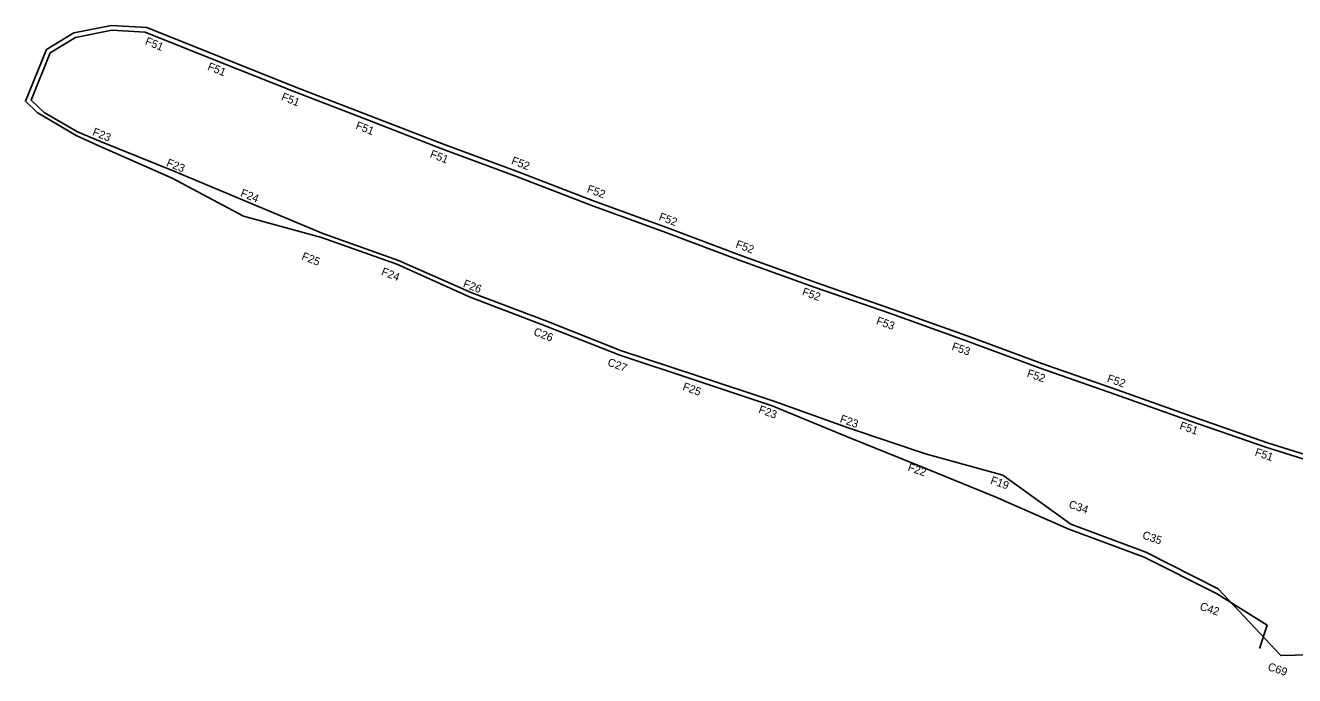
# Model space of a CAD drawing. Extents: x 2165700 to 2171741, y 206405 to 209505.
# Drawn here: x 2165700 to 2166493, y 209099 to 209505 of the extents above; entities that cross this region are included whole.
import ezdxf

# ---------------------------------------------------------------- set-up
doc = ezdxf.new("R2010")
doc.units = 0
for name, color, linetype in [('RD_PD_CstnLmt', 7, 'Continuous'), ('RD_PD_DR_ErosCtrl', 7, 'Continuous'), ('RD_PD_TX_CstnLmt', 7, 'Continuous')]:
    doc.layers.add(name, color=color, linetype=linetype)

msp = doc.modelspace()

# ---------------------------------------------------------------- linework, layer by layer
at = {"layer": 'RD_PD_CstnLmt'}
for points in [[(2165747.21, 209432.71), (2165732.71, 209438.76), (2165712.04, 209450.85), (2165703.77, 209458.61), (2165715.77, 209488.06), (2165731.53, 209497.76), (2165754.23, 209502.23), (2165775.05, 209501.06)], [(2165775.05, 209501.06), (2165821.27, 209482.56), (2165867.5, 209464.07), (2165913.95, 209446.14), (2165960.36, 209428.13), (2166007.07, 209410.87), (2166053.52, 209392.96), (2166100.26, 209375.82), (2166146.89, 209358.39), (2166193.74, 209341.54), (2166240.75, 209325.16), (2166287.63, 209308.42), (2166334.32, 209291.12), (2166381.27, 209274.58), (2166428.2, 209257.95), (2166475.23, 209241.61), (2166522.74, 209226.69)], [(2165747.21, 209432.71), (2165793.68, 209414), (2165839.83, 209394.47), (2165886.05, 209375.12), (2165933.27, 209358.3), (2165979.19, 209338.13), (2166026.05, 209320.39), (2166072.64, 209301.91), (2166120.24, 209286.15), (2166167.83, 209270.41), (2166214.97, 209253.46), (2166262.49, 209237.55), (2166310.85, 209224.11), (2166353.29, 209193.57), (2166400.26, 209175.98), (2166445.47, 209153.07), (2166484.54, 209111.46), (2166537.83, 209112.65)]]:
    msp.add_lwpolyline(points, dxfattribs=at)
at = {"layer": 'RD_PD_DR_ErosCtrl'}
for points in [[(2165707.57, 209450.82), (2165700.21, 209457.83), (2165713.36, 209490.1), (2165730.42, 209500.59), (2165754.02, 209505.25), (2165776.16, 209503.85)], [(2165776.16, 209503.85), (2165822.39, 209485.35), (2165868.6, 209466.86), (2165915.03, 209448.94), (2165961.43, 209430.93), (2166008.13, 209413.68), (2166054.58, 209395.77), (2166101.3, 209378.63), (2166147.93, 209361.21), (2166194.74, 209344.37), (2166241.75, 209327.99), (2166288.66, 209311.24), (2166335.34, 209293.94), (2166382.27, 209277.41), (2166429.19, 209260.78), (2166476.17, 209244.45), (2166523.61, 209229.56), (2166571.33, 209215.43), (2166619.35, 209201.82), (2166668.5, 209189), (2166668.5, 209189)], [(2165707.57, 209450.82), (2165732, 209436.48), (2165746.06, 209429.89), (2165792.01, 209409.85), (2165792.01, 209409.85), (2165836.5, 209386.09), (2165885.13, 209372.77), (2165932.36, 209355.94), (2165978.11, 209335.3), (2166024.93, 209317.48), (2166024.93, 209317.48), (2166024.95, 209317.47), (2166071.58, 209299.08), (2166119.2, 209283.34), (2166166.79, 209267.54), (2166213.15, 209248.37), (2166259.64, 209229.54), (2166306.15, 209210.68), (2166352.22, 209190.49), (2166399.23, 209172.94), (2166444.5, 209150.19), (2166476.04, 209130.33), (2166471.25, 209115.87)]]:
    msp.add_lwpolyline(points, dxfattribs=at)

# ---------------------------------------------------------------- texts
at = {"layer": 'RD_PD_TX_CstnLmt'}
for s, rotation, p in [('F51', 337.83882, (2165774.6, 209493.53)), ('F51', 338.07756, (2165813.59, 209477.66)), ('F51', 338.31629, (2165859.68, 209458.74)), ('F51', 338.55502, (2165906.14, 209440.82)), ('F23', 337.83882, (2165741.69, 209436.86)), ('F23', 338.07756, (2165787.92, 209417.56)), ('F51', 338.79375, (2165952.58, 209422.97)), ('F52', 339.03249, (2166003.4, 209418.8)), ('F52', 339.27122, (2166050.63, 209401.12)), ('F24', 338.31629, (2165834.16, 209398.64)), ('F52', 339.50995, (2166095.58, 209383.74)), ('F52', 339.74868, (2166143.53, 209366.56)), ('F25', 338.55502, (2165872.39, 209359.1)), ('F24', 338.79375, (2165922.17, 209349.5)), ('F26', 339.03249, (2165973.28, 209341.95)), ('F52', 339.98742, (2166185.09, 209336.89)), ('F53', 340.22615, (2166231.41, 209318.68)), ('C26', 339.27122, (2166017.29, 209311.89)), ('F53', 340.46488, (2166278.58, 209302.63)), ('C27', 339.50995, (2166063.51, 209292.85)), ('F52', 340.70361, (2166325.53, 209285.86)), ('F52', 340.94235, (2166375.61, 209282.6)), ('F25', 339.74868, (2166110.45, 209277.63)), ('F23', 339.98742, (2166157.86, 209263.29)), ('F23', 340.22615, (2166208.7, 209257.41)), ('F51', 341.18108, (2166420.94, 209253.07)), ('F51', 341.41981, (2166467.94, 209236.54)), ('F22', 340.46488, (2166251.1, 209227.15)), ('F19', 340.70361, (2166302.78, 209218.94)), ('C34', 340.94235, (2166351.65, 209203.95)), ('C35', 341.18108, (2166397.65, 209184.74)), ('C42', 341.41981, (2166433.55, 209140.19)), ('C69', 341.65854, (2166476.03, 209102.45))]:
    msp.add_text(s, height=5, rotation=rotation, dxfattribs=at).set_placement(p)

doc.saveas('drawing.dxf')
